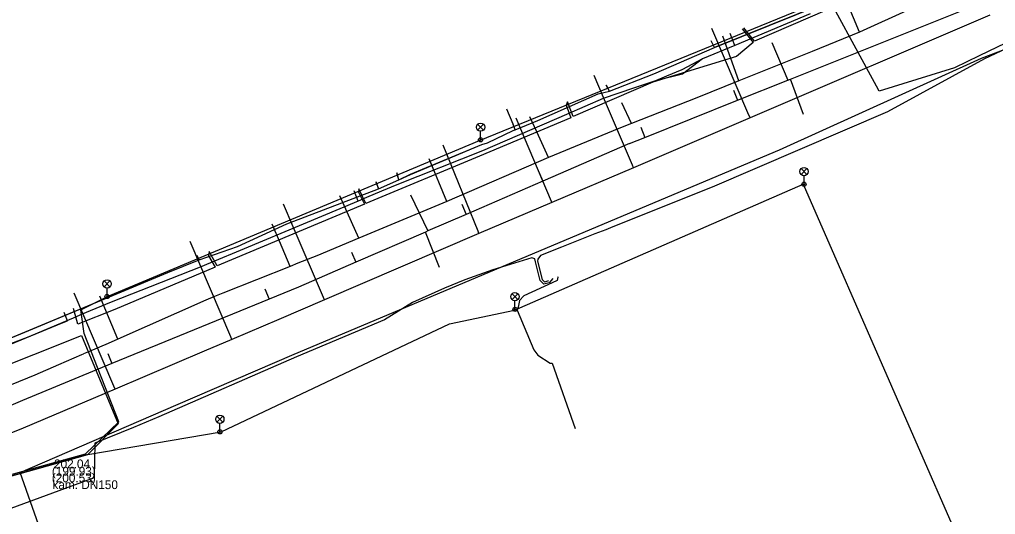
# Model space of a CAD drawing. Extents: x -596228 to -595156, y -1161235 to -1159373.
# Drawn here: x -595881.3 to -595792.7, y -1160742.2 to -1160697.2 of the extents above; entities that cross this region are included whole.
import ezdxf

# ---------------------------------------------------------------- set-up
doc = ezdxf.new("R2010")
doc.units = 0
for name, color, linetype in [('Vrstva 1', 7, 'Continuous'), ('Vrstva 12', 7, 'Continuous'), ('Vrstva 14', 7, 'Continuous'), ('Vrstva 19', 7, 'Continuous'), ('Vrstva 33', 7, 'Continuous'), ('Vrstva 42', 7, 'Continuous'), ('Vrstva 55', 7, 'Continuous'), ('Vrstva 58', 7, 'Continuous'), ('Vrstva 9', 7, 'Continuous')]:
    doc.layers.add(name, color=color, linetype=linetype)

msp = doc.modelspace()

# ---------------------------------------------------------------- linework, layer by layer
at = {"layer": 'Vrstva 1'}
for p, q in [((-595813.021, -1160699.319), (-595811.586, -1160702.729)), ((-595810.145, -1160705.844), (-595811.354, -1160702.636)), ((-595845.829, -1160713.142), (-595844.253, -1160716.426)), ((-595843.22, -1160719.735), (-595844.47, -1160716.52))]:
    msp.add_line(p, q, dxfattribs=at)
at = {"layer": 'Vrstva 12'}
for p, q in [((-595809.54, -1160696.71), (-595816.39, -1160699.57)), ((-595816.39, -1160699.57), (-595816.83, -1160698.5)), ((-595816.39, -1160699.57), (-595819.34, -1160700.8)), ((-595818.23, -1160699.77), (-595818.51, -1160699.21)), ((-595819.34, -1160700.8), (-595821.21, -1160701.79)), ((-595827.77, -1160703.73), (-595828.06, -1160703.2)), ((-595823.61, -1160702.79), (-595825.5, -1160703.43)), ((-595836.35, -1160707.23), (-595836.51, -1160706.76)), ((-595846.89, -1160711.79), (-595847.06, -1160711.16)), ((-595846.89, -1160711.79), (-595845.84, -1160711.28)), ((-595848.99, -1160711.96), (-595848.74, -1160712.59)), ((-595848.74, -1160712.59), (-595846.89, -1160711.79)), ((-595850.59, -1160713.71), (-595850.97, -1160712.79)), ((-595850.59, -1160713.71), (-595855.59, -1160715.8)), ((-595855.59, -1160715.8), (-595860.94, -1160718.04)), ((-595865.04, -1160719.06), (-595865.18, -1160718.73)), ((-595876.25, -1160724.25), (-595880.5, -1160726.03)), ((-595880.5, -1160726.03), (-595883.46, -1160727.17))]:
    msp.add_line(p, q, dxfattribs=at)
for points in [[(-595808.18, -1160692.44), (-595807.18, -1160694.55), (-595807.3, -1160694.98), (-595807.56, -1160695.34), (-595808.31, -1160695.76), (-595818.23, -1160699.77)], [(-595785.98, -1160696.61), (-595786.99, -1160697.05), (-595794.2, -1160700.51), (-595796.46, -1160701.6), (-595803.29, -1160703.74), (-595803.54, -1160703.27), (-595807.23, -1160696.51), (-595807.5, -1160695.86)], [(-595862.55, -1160791.53), (-595869.91, -1160770.64), (-595881.29, -1160738.36), (-595867.15, -1160732.24), (-595856.41, -1160727.6), (-595812.34, -1160709.06), (-595794, -1160700.74), (-595786.52, -1160697.9), (-595785.77, -1160697.61)], [(-595827.77, -1160703.73), (-595823.75, -1160702.15), (-595818.23, -1160699.77)], [(-595819.34, -1160700.8), (-595821.15, -1160702.2), (-595823.61, -1160702.79)], [(-595821.21, -1160701.79), (-595822.59, -1160702.37), (-595823.61, -1160702.79)], [(-595825.5, -1160703.43), (-595827.02, -1160703.95), (-595828.34, -1160704.4), (-595831.69, -1160705.85), (-595839.31, -1160709.14), (-595847.08, -1160712.25), (-595848.47, -1160712.82)], [(-595836.35, -1160707.23), (-595834.28, -1160706.38), (-595828.81, -1160703.98), (-595827.77, -1160703.73)], [(-595845.84, -1160711.28), (-595839.36, -1160708.58), (-595838.84, -1160708.42), (-595836.53, -1160707.3), (-595836.35, -1160707.23)], [(-595865.04, -1160719.06), (-595861.56, -1160717.85), (-595857.06, -1160715.77), (-595848.74, -1160712.59)], [(-595848.47, -1160712.82), (-595849.85, -1160713.4), (-595850.59, -1160713.71)], [(-595860.94, -1160718.04), (-595864.01, -1160719.32), (-595864.93, -1160719.7), (-595873.03, -1160722.89), (-595875.79, -1160724.05), (-595876.25, -1160724.25)], [(-595881.23, -1160725.75), (-595867.86, -1160720.21), (-595865.04, -1160719.06)], [(-595884.86, -1160726.96), (-595884.4, -1160727.07), (-595881.23, -1160725.75)]]:
    msp.add_lwpolyline(points, dxfattribs=at)
at = {"layer": 'Vrstva 14'}
msp.add_line((-595881.004, -1160734.33), (-595886.451, -1160736.489), dxfattribs=at)
for points in [[(-595793.243, -1160696.845), (-595815.008, -1160706.159), (-595825.585, -1160710.685), (-595833.004, -1160713.85), (-595839.625, -1160716.663), (-595853.638, -1160722.689), (-595857.793, -1160724.467), (-595862.064, -1160726.281), (-595864.566, -1160727.344), (-595872.661, -1160730.783), (-595881.004, -1160734.33)], [(-595815.008, -1160706.159), (-595815.212, -1160705.683), (-595818.483, -1160698.039)], [(-595825.585, -1160710.685), (-595825.68, -1160710.464), (-595828.31, -1160704.318), (-595829.169, -1160702.309)], [(-595833.004, -1160713.85), (-595833.053, -1160713.742), (-595836.243, -1160706.19)], [(-595839.625, -1160716.663), (-595839.702, -1160716.436), (-595842.884, -1160708.621)], [(-595853.638, -1160722.689), (-595856.483, -1160716.042), (-595857.362, -1160713.986)], [(-595862.064, -1160726.281), (-595862.167, -1160726.039), (-595865.842, -1160717.387)], [(-595872.661, -1160730.783), (-595872.777, -1160730.511), (-595876.364, -1160722.065)]]:
    msp.add_lwpolyline(points, dxfattribs=at)
at = {"layer": 'Vrstva 19'}
for p, q in [((-595816.03, -1160702.8), (-595817.49, -1160698.73)), ((-595825.78, -1160706.68), (-595826.64, -1160704.78)), ((-595842.55, -1160713.75), (-595844.16, -1160709.87)), ((-595850.52, -1160717.08), (-595852.26, -1160713.24)), ((-595872.41, -1160726.25), (-595874.05, -1160722.33))]:
    msp.add_line(p, q, dxfattribs=at)
for points in [[(-595791.14, -1160692), (-595791.61, -1160692.22), (-595805.09, -1160698.36), (-595809.37, -1160700.14), (-595816.03, -1160702.8), (-595819.85, -1160704.33), (-595825.78, -1160706.68), (-595826.92, -1160707.13), (-595833.3, -1160709.74), (-595842.55, -1160713.75), (-595850.52, -1160717.08), (-595854.36, -1160718.68), (-595856.08, -1160719.36), (-595856.77, -1160719.64), (-595862.89, -1160722.07), (-595863.65, -1160722.39), (-595864.41, -1160722.71), (-595872.41, -1160726.25), (-595873.3, -1160726.63), (-595875.09, -1160727.39), (-595875.53, -1160727.58)], [(-595805.09, -1160698.36), (-595806.57, -1160694.81)], [(-595833.3, -1160709.74), (-595834.38, -1160707.41), (-595835, -1160706.07)], [(-595856.77, -1160719.64), (-595857.74, -1160717.35), (-595857.83, -1160717.14), (-595858.22, -1160716.23), (-595858.4, -1160715.81)], [(-595892.57, -1160734.72), (-595891.52, -1160734.29), (-595888.97, -1160733.21), (-595887.72, -1160732.68), (-595879.93, -1160729.49), (-595877.77, -1160728.55), (-595877.08, -1160728.26), (-595875.68, -1160727.65), (-595875.53, -1160727.58)]]:
    msp.add_lwpolyline(points, dxfattribs=at)
at = {"layer": 'Vrstva 33'}
for p, q in [((-595839.745, -1160706.735), (-595839.215, -1160707.265)), ((-595839.745, -1160707.265), (-595839.215, -1160706.735)), ((-595839.48, -1160708.15), (-595839.48, -1160707.375)), ((-595810.375, -1160710.765), (-595809.845, -1160711.295)), ((-595810.375, -1160711.295), (-595809.845, -1160710.765)), ((-595810.11, -1160712.18), (-595810.11, -1160711.405)), ((-595873.655, -1160720.965), (-595873.125, -1160721.495)), ((-595873.655, -1160721.495), (-595873.125, -1160720.965)), ((-595873.39, -1160722.38), (-595873.39, -1160721.605)), ((-595836.625, -1160722.125), (-595836.095, -1160722.655)), ((-595836.625, -1160722.655), (-595836.095, -1160722.125)), ((-595836.36, -1160723.54), (-595836.36, -1160722.765)), ((-595863.415, -1160733.255), (-595862.885, -1160733.785)), ((-595863.415, -1160733.785), (-595862.885, -1160733.255)), ((-595863.15, -1160734.67), (-595863.15, -1160733.895))]:
    msp.add_line(p, q, dxfattribs=at)
for centre, radius in [((-595839.48, -1160707), 0.375), ((-595839.48, -1160708.15), 0.19), ((-595839.48, -1160708.15), 0.05), ((-595810.11, -1160711.03), 0.375), ((-595810.11, -1160712.18), 0.19), ((-595810.11, -1160712.18), 0.05), ((-595873.39, -1160721.23), 0.375), ((-595836.36, -1160722.39), 0.375), ((-595873.39, -1160722.38), 0.19), ((-595873.39, -1160722.38), 0.05), ((-595836.36, -1160723.54), 0.19), ((-595836.36, -1160723.54), 0.05), ((-595863.15, -1160733.52), 0.375), ((-595863.15, -1160734.67), 0.19), ((-595863.15, -1160734.67), 0.05)]:
    msp.add_circle(centre, radius, dxfattribs=at)
at = {"layer": 'Vrstva 42'}
msp.add_line((-595832.98, -1160728.42), (-595830.89, -1160734.36), dxfattribs=at)
for points in [[(-595792.627, -1160677.175), (-595793.25, -1160677.391), (-595790.302, -1160684.356), (-595789.952, -1160685.36), (-595789.408, -1160687.038), (-595789.386, -1160687.449), (-595789.383, -1160689.032), (-595786.113, -1160696.439), (-595786.288, -1160696.706), (-595786.84, -1160697.551), (-595793.735, -1160700.796), (-595802.548, -1160705.598), (-595818.461, -1160712.44), (-595827.486, -1160716.044), (-595828.11, -1160716.31), (-595829.1, -1160716.7)], [(-595816.004, -1160677.665), (-595815.619, -1160677.665), (-595812.688, -1160683.919), (-595811.402, -1160686.434), (-595807.727, -1160695.37), (-595808.023, -1160696.356), (-595814.612, -1160699.201), (-595815.565, -1160697.976)], [(-595815.734, -1160698.066), (-595814.732, -1160699.306), (-595816.23, -1160700.594), (-595823.828, -1160702.907), (-595831.074, -1160706.046), (-595831.589, -1160704.69), (-595831.717, -1160704.987), (-595831.283, -1160706.158), (-595839.589, -1160709.644), (-595849.908, -1160713.921), (-595850.519, -1160712.587), (-595850.56, -1160712.897), (-595850.031, -1160713.994), (-595863.408, -1160719.596), (-595864.124, -1160718.285), (-595864.176, -1160718.697), (-595863.59, -1160719.718), (-595872.682, -1160723.55), (-595876.051, -1160724.902), (-595876.442, -1160723.476)], [(-595829.1, -1160716.7), (-595832.12, -1160717.91), (-595834.04, -1160718.64), (-595834.267, -1160718.984), (-595834.313, -1160719.176), (-595833.9, -1160720.817), (-595833.672, -1160721.03), (-595833.356, -1160720.951), (-595833.305, -1160720.887)], [(-595832.932, -1160720.752), (-595833.244, -1160721.129), (-595833.728, -1160721.25), (-595834.08, -1160720.923), (-595834.507, -1160719.224), (-595834.55, -1160718.95), (-595834.836, -1160718.86), (-595838.361, -1160719.942), (-595840.923, -1160720.85), (-595842.743, -1160721.615), (-595845.652, -1160722.926), (-595848.213, -1160724.486), (-595856.187, -1160727.856), (-595868.702, -1160733.3), (-595870.982, -1160734.273), (-595874.511, -1160735.698), (-595874.569, -1160738.85), (-595882.702, -1160741.846)], [(-595832.49, -1160720.56), (-595832.45, -1160720.63), (-595832.54, -1160720.91), (-595832.97, -1160721.13), (-595835.56, -1160722.3), (-595835.93, -1160722.75), (-595836.06, -1160723.35), (-595836.15, -1160723.63), (-595834.65, -1160727.23), (-595834.27, -1160727.7), (-595833.15, -1160728.44), (-595832.98, -1160728.42)], [(-595882.208, -1160726.723), (-595877.9, -1160724.955), (-595876.991, -1160724.571), (-595877.288, -1160723.831)]]:
    msp.add_lwpolyline(points, dxfattribs=at)
at = {"layer": 'Vrstva 55'}
for points in [[(-595889.79, -1160745.95), (-595891.36, -1160746.06), (-595892.42, -1160743.16), (-595891.92, -1160741.26), (-595875.35, -1160736.65), (-595872.33, -1160733.76), (-595875.48, -1160725.74), (-595875.785, -1160723.596), (-595873.304, -1160722.355), (-595839.562, -1160708.213), (-595811.03, -1160696.553), (-595790.3, -1160687.72), (-595790.51, -1160686.78), (-595788.97, -1160684.34)], [(-595889.79, -1160745.95), (-595891.36, -1160746.06), (-595890.68, -1160742.18), (-595891.55, -1160741.32), (-595875.14, -1160736.73), (-595863.03, -1160734.65), (-595842.305, -1160724.861), (-595836.396, -1160723.626), (-595810.202, -1160712.161), (-595794.144, -1160748.847), (-595820.885, -1160760.263), (-595826.343, -1160763.884), (-595835.327, -1160767.526), (-595847.836, -1160771.52)], [(-595888.13, -1160725.02), (-595887.47, -1160725.094), (-595887.47, -1160725.89), (-595886.36, -1160728.33), (-595884.41, -1160729.36), (-595875.71, -1160725.93), (-595872.39, -1160733.93), (-595875.14, -1160736.73), (-595891.55, -1160741.32), (-595890.68, -1160742.18), (-595890.97, -1160743.47), (-595891.52, -1160746.45), (-595889.79, -1160745.95)]]:
    msp.add_lwpolyline(points, dxfattribs=at)
at = {"layer": 'Vrstva 58'}
for p, q in [((-595818.23, -1160699.77), (-595818.54, -1160699.16)), ((-595827.77, -1160703.73), (-595828.07, -1160703.19)), ((-595846.89, -1160711.79), (-595847.07, -1160711.14)), ((-595849, -1160711.94), (-595848.74, -1160712.59)), ((-595848.74, -1160712.59), (-595846.89, -1160711.79)), ((-595865.04, -1160719.06), (-595865.21, -1160718.66))]:
    msp.add_line(p, q, dxfattribs=at)
for points in [[(-595808.18, -1160692.44), (-595807.18, -1160694.55), (-595807.3, -1160694.98), (-595807.56, -1160695.34), (-595808.31, -1160695.76), (-595818.23, -1160699.77)], [(-595884.4, -1160727.07), (-595867.86, -1160720.21), (-595865.04, -1160719.06), (-595861.56, -1160717.85), (-595857.07, -1160715.77), (-595848.74, -1160712.59), (-595846.89, -1160711.79), (-595845.84, -1160711.29), (-595839.36, -1160708.58), (-595838.84, -1160708.42), (-595836.53, -1160707.3), (-595836.35, -1160707.23), (-595834.28, -1160706.38), (-595828.81, -1160703.98), (-595827.77, -1160703.73), (-595823.75, -1160702.15), (-595818.23, -1160699.77), (-595808.31, -1160695.76), (-595807.56, -1160695.34)], [(-595827.77, -1160703.73), (-595823.75, -1160702.15), (-595818.23, -1160699.77)], [(-595836.35, -1160707.23), (-595834.28, -1160706.38), (-595828.81, -1160703.98), (-595827.77, -1160703.73)], [(-595836.35, -1160707.23), (-595836.52, -1160706.74), (-595837.1, -1160705.36)], [(-595846.89, -1160711.79), (-595845.84, -1160711.29), (-595839.36, -1160708.58), (-595838.84, -1160708.42), (-595836.53, -1160707.3), (-595836.35, -1160707.23)], [(-595865.04, -1160719.06), (-595861.56, -1160717.85), (-595857.07, -1160715.77), (-595848.74, -1160712.59)], [(-595884.86, -1160726.96), (-595884.4, -1160727.07), (-595867.86, -1160720.21), (-595865.04, -1160719.06)]]:
    msp.add_lwpolyline(points, dxfattribs=at)
at = {"layer": 'Vrstva 9'}
for p, q in [((-595816.527, -1160703.628), (-595816.153, -1160704.56)), ((-595824.925, -1160707.001), (-595824.552, -1160707.929)), ((-595834.231, -1160710.99), (-595833.833, -1160711.908)), ((-595841.18, -1160714.003), (-595840.782, -1160714.921)), ((-595851.21, -1160718.352), (-595850.813, -1160719.27)), ((-595859.054, -1160721.69), (-595858.675, -1160722.615)), ((-595873.332, -1160727.538), (-595872.953, -1160728.464)), ((-595881.08, -1160731.81), (-595889.188, -1160735.27))]:
    msp.add_line(p, q, dxfattribs=at)
for points in [[(-595825.95, -1160708.49), (-595824.552, -1160707.929), (-595816.153, -1160704.56), (-595811.586, -1160702.729), (-595811.354, -1160702.636), (-595791.52, -1160694.68)], [(-595825.95, -1160708.49), (-595833.833, -1160711.908), (-595840.782, -1160714.921), (-595844.253, -1160716.425), (-595844.47, -1160716.52), (-595850.813, -1160719.27), (-595856.022, -1160721.529)], [(-595856.022, -1160721.529), (-595858.675, -1160722.615), (-595872.953, -1160728.464), (-595881.08, -1160731.81)]]:
    msp.add_lwpolyline(points, dxfattribs=at)

# ---------------------------------------------------------------- texts
at = {"layer": 'Vrstva 12'}
for s, p in [('202.04', (-595878.208, -1160737.973)), ('(199.93)', (-595878.404, -1160738.64)), ('(200.53)', (-595878.408, -1160739.241)), ('kam. DN150', (-595878.351, -1160739.862))]:
    msp.add_text(s, height=0.8, dxfattribs=at).set_placement(p)

doc.saveas('drawing.dxf')
